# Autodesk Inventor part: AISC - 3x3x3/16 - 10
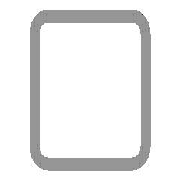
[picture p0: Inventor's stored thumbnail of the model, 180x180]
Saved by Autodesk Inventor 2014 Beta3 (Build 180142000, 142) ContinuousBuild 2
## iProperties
IsCustomPart: 1
Created: 2010-12
Part Number: AISC - 3x3x3/16 - 10
Material: Steel, Mild
Description: Tube
Document SubType Name: Modeling
Standard: ANSI
Designer: Beta-8540w
Standards Organization: ANSI
Language: en-US
Size Designation: 3x3x3/16
Categories: <MemberInstance><Categories><Category DisplayName="Structural Shapes" InternalName="089c4875-fa83-4c05-b084-43b9cc11f5ed" Mnemonic="GRDR"><CategoryParameter Dis
Stock Number: 3x3x3/16
Density: 7.86 g/cm^3
Appearance: Steel
_CCFamilyMember: 9
_CCFamilyDisplayName: ANSI AISC (Square) - Tube
_FrameMemberDoc: Frame Member File
_Version: 15.0.0
_GetPNFromCC: 1
G_L: 10.000 in
G_W: 3.000 in
G_H: 3.000 in
Author: Beta-8540w
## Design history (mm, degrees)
node "Start plane"
node "End plane"
sketch "Sketch"
  geometry: L1 (-38.1, -28.575)-(-38.1, 28.575); L2 (-28.575, 38.1)-(28.575, 38.1); L3 (38.1, 28.575)-(38.1, -28.575); L4 (28.575, -38.1)-(-28.575, -38.1); L5 (-28.575, 33.337)-(28.575, 33.338); L6 (33.338, 28.575)-(33.338, -28.575); L7 (28.575, -33.337)-(-28.575, -33.338); L8 (-33.338, -28.575)-(-33.338, 28.575); L9 (0, 56.102)-(0, -56.102) reference; L10 (-56.102, 0)-(56.102, 0) reference; A1 r 9.525 centre (-28.575, -28.575) between (-38.1, -28.575) and (-28.575, -38.1); A2 r 9.525 centre (-28.575, 28.575) between (-28.575, 38.1) and (-38.1, 28.575); A3 r 9.525 centre (28.575, 28.575) between (38.1, 28.575) and (28.575, 38.1); A4 r 9.525 centre (28.575, -28.575) between (28.575, -38.1) and (38.1, -28.575); A5 r 4.763 centre (-28.575, 28.575) between (-28.575, 33.337) and (-33.338, 28.575); A6 r 4.763 centre (28.575, 28.575) between (33.338, 28.575) and (28.575, 33.338); A7 r 4.763 centre (28.575, -28.575) between (28.575, -33.337) and (33.338, -28.575); A8 r 4.763 centre (-28.575, -28.575) between (-33.338, -28.575) and (-28.575, -33.338)
  constraints: 16 end point, 16 point on circle, 8 centre point, 8 tangent, 4 parallel, 3 equal radius, 2 perpendicular, 7 other
  dimensions: "d10" = 76.2 distance between parallel lines of L2 L4 (= G_H); "d11" = 76.2 distance between parallel lines of L1 L3 (= G_W); "d12" = 4.7625 distance between parallel lines of L3 L6 (= G_T); "d15" = 38.1 distance between parallel lines of L2 L10 (= 0.5 x d10); "d16" = 38.1 distance between parallel lines of L9 L3 (= 0.5 x d11); "d17" = 9.525 radius of A1 (= G_IR)
extrude "Body" new body sketch "Sketch" stored distance "d3" = 254 (= G_L); taper "d4" = 0 deg
node "Driven Length"
  sketch "Sketch3"
    geometry: L1 (0, 0)-(10, 0) reference
    constraints: 2 end point, 1 horizontal
  workplane "Work Plane3"
  sketch "Sketch4"
    geometry: L1 (-2, 0)-(12, 0) reference; L2 (-2, 254)-(12, 254) reference
    dimensions: "d19" = 254 distance between parallel lines of L1 L2 (derived)
body "Solid1"
other parameters: "G_W" = 76.2 [user parameter; used in 1 equation term], "G_H" = 76.2 [user parameter; used in 1 equation term], "G_T" = 4.7625 [user parameter; used in 1 equation term], "G_IR" = 9.525 [user parameter; used in 1 equation term], "G_L" = 254 [user parameter; used in 1 equation term], "G_OFFSET_START" = 0 [user parameter; used in 1 equation term], "G_OFFSET_END" = 0 [user parameter; used in 1 equation term], "d13" = 0 (computed from G_OFFSET_START), "d14" = 254 (= G_OFFSET_END + B_L), "B_L" = 254 [user parameter; used in 1 equation term], "d18" = 90 deg
